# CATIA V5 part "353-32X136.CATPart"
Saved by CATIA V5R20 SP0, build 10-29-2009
Part number: 353-32X136
Definition: NONE
Nomenclature: 353-32X136
Source: Unknown
Description: 353-32X136
Bounding box of the stored display mesh (mm): x -7 to 129, y -22.5 to 22.5, z -22.5 to 22.5
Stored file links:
  C:\Users\Utente\Desktop\IO LAVORO\3D X SITO CF\X SITO\PLASTICA\353\353-32X136.CATPart
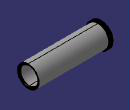
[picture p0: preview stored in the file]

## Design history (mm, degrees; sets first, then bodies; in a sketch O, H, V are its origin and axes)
Body1 "353-32X136" (main body)
  Solid1: solid without history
